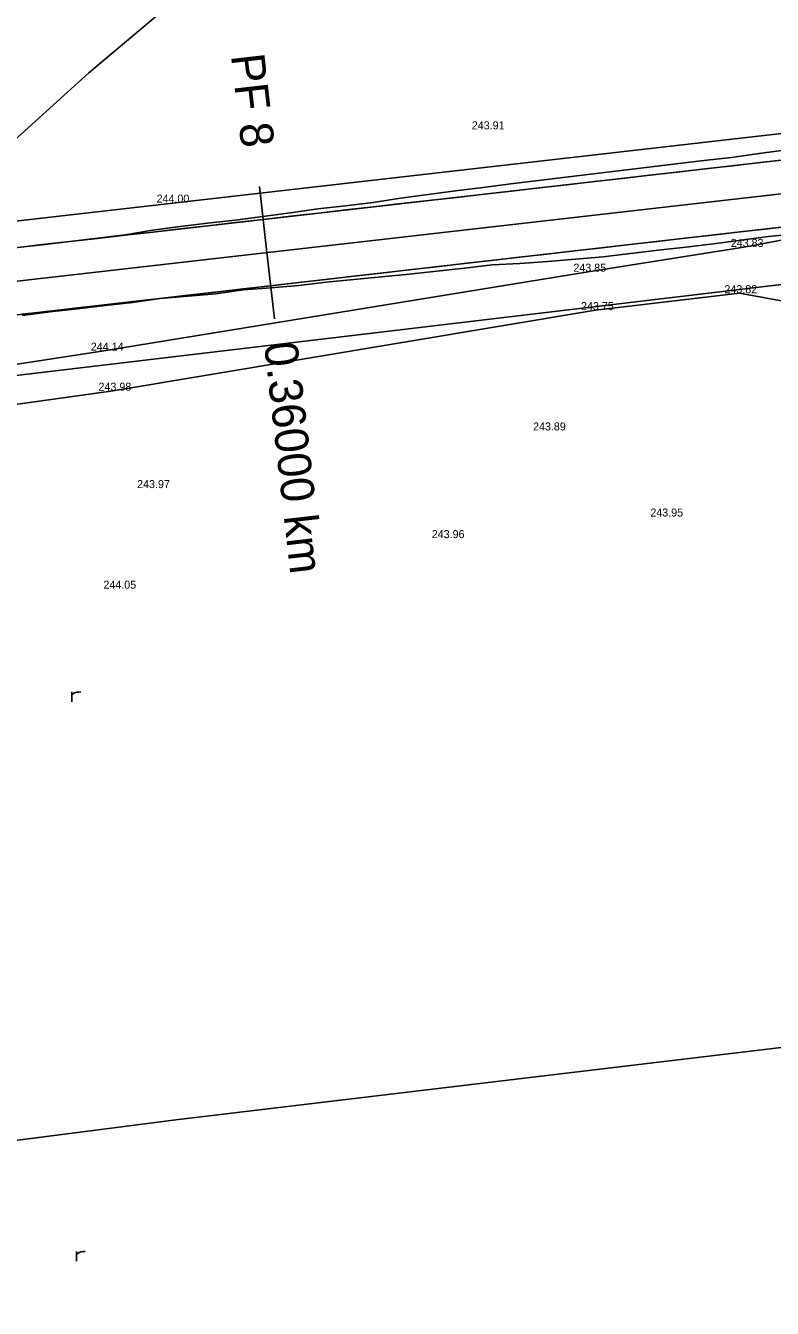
# Model space of a CAD drawing. Extents: x -555887 to -552101, y -1100251 to -1096546.
# Drawn here: x -554433.8 to -554377.8, y -1097745.7 to -1097649.6 of the extents above; entities that cross this region are included whole.
import ezdxf

# ---------------------------------------------------------------- set-up
doc = ezdxf.new("R2010")
doc.units = 0
for name, color, linetype in [('PARCELY_cesty', 7, 'Continuous'), ('POLYGONY_SITUACE_PF', 7, 'Continuous'), ('POLYGONY_SITUACE_PF_POPISY', 7, 'Continuous'), ('POLYGONY_SITUACE_PO', 7, 'Continuous'), ('vrstevnice', 7, 'Continuous'), ('Výškopis', 7, 'Continuous'), ('ZSST', 7, 'Continuous'), ('zájem', 7, 'Continuous')]:
    doc.layers.add(name, color=color, linetype=linetype)

msp = doc.modelspace()

# ---------------------------------------------------------------- linework, layer by layer
at = {"layer": 'PARCELY_cesty'}
msp.add_lwpolyline([(-554491.8, -1097670.76), (-554258.37, -1097644.02)], dxfattribs=at)
at = {"layer": 'POLYGONY_SITUACE_PF'}
for p, q in [((-554416.301, -1097661.61), (-554415.732, -1097666.578)), ((-554415.732, -1097666.578), (-554415.163, -1097671.545))]:
    msp.add_line(p, q, dxfattribs=at)
at = {"layer": 'POLYGONY_SITUACE_PO'}
for p, q in [((-554247.533, -1097644.797), (-554424.295, -1097665.042)), ((-554490.653, -1097675.159), (-554241.626, -1097646.637)), ((-554444.424, -1097672.38), (-554255.551, -1097650.748)), ((-554380.901, -1097659.437), (-554382.97, -1097659.685)), ((-554378.837, -1097659.153), (-554380.901, -1097659.437)), ((-554376.772, -1097658.87), (-554378.837, -1097659.153)), ((-554378.76, -1097659.827), (-554376.69, -1097659.59)), ((-554389.178, -1097660.411), (-554391.245, -1097660.665)), ((-554387.109, -1097660.164), (-554389.178, -1097660.411)), ((-554385.04, -1097659.922), (-554387.109, -1097660.164)), ((-554387.039, -1097660.775), (-554384.969, -1097660.538)), ((-554382.97, -1097659.685), (-554385.04, -1097659.922)), ((-554384.969, -1097660.538), (-554382.899, -1097660.301)), ((-554382.899, -1097660.301), (-554380.829, -1097660.064)), ((-554380.829, -1097660.064), (-554378.76, -1097659.827)), ((-554397.45, -1097661.421), (-554399.515, -1097661.693)), ((-554395.382, -1097661.163), (-554397.45, -1097661.421)), ((-554393.314, -1097660.916), (-554395.382, -1097661.163)), ((-554395.318, -1097661.723), (-554393.248, -1097661.486)), ((-554391.245, -1097660.665), (-554393.314, -1097660.916)), ((-554393.248, -1097661.486), (-554391.178, -1097661.249)), ((-554391.178, -1097661.249), (-554389.109, -1097661.012)), ((-554389.109, -1097661.012), (-554387.039, -1097660.775)), ((-554405.713, -1097662.509), (-554407.774, -1097662.82)), ((-554403.649, -1097662.217), (-554405.713, -1097662.509)), ((-554401.583, -1097661.947), (-554403.649, -1097662.217)), ((-554403.597, -1097662.672), (-554401.527, -1097662.435)), ((-554399.515, -1097661.693), (-554401.583, -1097661.947)), ((-554401.527, -1097662.435), (-554399.458, -1097662.197)), ((-554399.458, -1097662.197), (-554397.388, -1097661.96)), ((-554397.388, -1097661.96), (-554395.318, -1097661.723)), ((-554411.913, -1097663.301), (-554413.977, -1097663.589)), ((-554409.842, -1097663.07), (-554411.913, -1097663.301)), ((-554411.876, -1097663.62), (-554409.807, -1097663.383)), ((-554407.774, -1097662.82), (-554409.842, -1097663.07)), ((-554409.807, -1097663.383), (-554407.737, -1097663.146)), ((-554407.737, -1097663.146), (-554405.667, -1097662.909)), ((-554405.667, -1097662.909), (-554403.597, -1097662.672)), ((-554420.178, -1097664.375), (-554422.245, -1097664.632)), ((-554418.108, -1097664.142), (-554420.178, -1097664.375)), ((-554420.156, -1097664.568), (-554418.086, -1097664.331)), ((-554416.04, -1097663.882), (-554418.108, -1097664.142)), ((-554418.086, -1097664.331), (-554416.016, -1097664.094)), ((-554413.977, -1097663.589), (-554416.04, -1097663.882)), ((-554416.016, -1097664.094), (-554413.946, -1097663.857)), ((-554413.946, -1097663.857), (-554411.876, -1097663.62)), ((-554426.37, -1097665.237), (-554428.436, -1097665.506)), ((-554428.435, -1097665.516), (-554426.365, -1097665.279)), ((-554426.365, -1097665.279), (-554428.435, -1097665.516)), ((-554424.313, -1097664.889), (-554426.37, -1097665.237)), ((-554426.365, -1097665.279), (-554424.295, -1097665.042)), ((-554424.295, -1097665.042), (-554426.365, -1097665.279)), ((-554422.245, -1097664.632), (-554424.313, -1097664.889)), ((-554424.295, -1097665.042), (-554422.225, -1097664.805)), ((-554422.225, -1097664.805), (-554420.156, -1097664.568)), ((-554384.4, -1097665.506), (-554382.33, -1097665.269)), ((-554382.33, -1097665.269), (-554380.26, -1097665.031)), ((-554380.26, -1097665.031), (-554378.191, -1097664.794)), ((-554380.191, -1097665.641), (-554378.123, -1097665.382)), ((-554378.191, -1097664.794), (-554376.121, -1097664.557)), ((-554378.123, -1097665.382), (-554376.05, -1097665.174)), ((-554434.644, -1097666.227), (-554432.574, -1097665.99)), ((-554432.574, -1097665.99), (-554434.644, -1097666.227)), ((-554432.577, -1097665.971), (-554433.948, -1097666.148)), ((-554430.505, -1097665.746), (-554432.577, -1097665.971)), ((-554432.574, -1097665.99), (-554430.505, -1097665.753)), ((-554430.505, -1097665.753), (-554432.574, -1097665.99)), ((-554428.436, -1097665.506), (-554430.505, -1097665.746)), ((-554430.505, -1097665.753), (-554428.435, -1097665.516)), ((-554428.435, -1097665.516), (-554430.505, -1097665.753)), ((-554392.679, -1097666.454), (-554390.609, -1097666.217)), ((-554390.609, -1097666.217), (-554388.54, -1097665.98)), ((-554388.54, -1097665.98), (-554386.47, -1097665.743)), ((-554386.47, -1097665.743), (-554384.4, -1097665.506)), ((-554386.394, -1097666.406), (-554384.323, -1097666.176)), ((-554384.323, -1097666.176), (-554382.255, -1097665.926)), ((-554382.255, -1097665.926), (-554380.191, -1097665.641)), ((-554400.959, -1097667.402), (-554398.889, -1097667.165)), ((-554398.889, -1097667.165), (-554396.819, -1097666.928)), ((-554396.819, -1097666.928), (-554394.749, -1097666.691)), ((-554396.767, -1097667.383), (-554394.686, -1097667.241)), ((-554394.749, -1097666.691), (-554392.679, -1097666.454)), ((-554394.686, -1097667.241), (-554392.608, -1097667.073)), ((-554392.608, -1097667.073), (-554390.531, -1097666.9)), ((-554390.531, -1097666.9), (-554388.464, -1097666.638)), ((-554388.464, -1097666.638), (-554386.394, -1097666.406)), ((-554409.238, -1097668.35), (-554407.168, -1097668.113)), ((-554407.168, -1097668.113), (-554405.098, -1097667.876)), ((-554407.136, -1097668.395), (-554405.063, -1097668.182)), ((-554405.098, -1097667.876), (-554403.028, -1097667.639)), ((-554405.063, -1097668.182), (-554402.991, -1097667.969)), ((-554403.028, -1097667.639), (-554400.959, -1097667.402)), ((-554402.991, -1097667.969), (-554400.918, -1097667.755)), ((-554400.918, -1097667.755), (-554398.851, -1097667.496)), ((-554398.851, -1097667.496), (-554396.767, -1097667.383)), ((-554417.517, -1097669.299), (-554415.447, -1097669.061)), ((-554417.508, -1097669.38), (-554415.43, -1097669.214)), ((-554415.447, -1097669.061), (-554413.377, -1097668.824)), ((-554415.43, -1097669.214), (-554413.353, -1097669.033)), ((-554413.377, -1097668.824), (-554411.308, -1097668.587)), ((-554413.353, -1097669.033), (-554411.284, -1097668.796)), ((-554411.308, -1097668.587), (-554409.238, -1097668.35)), ((-554411.284, -1097668.796), (-554409.208, -1097668.606)), ((-554409.208, -1097668.606), (-554407.136, -1097668.395)), ((-554427.866, -1097670.484), (-554425.796, -1097670.247)), ((-554425.796, -1097670.247), (-554423.726, -1097670.01)), ((-554425.787, -1097670.329), (-554423.927, -1097670.033)), ((-554423.927, -1097670.033), (-554423.725, -1097670.018)), ((-554423.726, -1097670.01), (-554421.657, -1097669.773)), ((-554423.725, -1097670.018), (-554421.649, -1097669.836)), ((-554421.657, -1097669.773), (-554419.587, -1097669.536)), ((-554421.649, -1097669.836), (-554419.572, -1097669.666)), ((-554419.587, -1097669.536), (-554417.517, -1097669.299)), ((-554419.572, -1097669.666), (-554417.508, -1097669.38)), ((-554434.075, -1097671.195), (-554432.006, -1097670.958)), ((-554434.065, -1097671.281), (-554431.997, -1097671.029)), ((-554432.006, -1097670.958), (-554429.936, -1097670.721)), ((-554431.997, -1097671.029), (-554429.928, -1097670.791)), ((-554429.936, -1097670.721), (-554427.866, -1097670.484)), ((-554429.928, -1097670.791), (-554427.858, -1097670.55)), ((-554427.858, -1097670.55), (-554425.787, -1097670.329))]:
    msp.add_line(p, q, dxfattribs=at)
at = {"layer": 'vrstevnice'}
msp.add_lwpolyline([(-554436.587, -1097659.868), (-554429.094, -1097653.099), (-554419.995, -1097645.438)], dxfattribs=at)
at = {"layer": 'ZSST'}
for points in [[(-554454.89, -1097678.09), (-554427.97, -1097673.93), (-554391.64, -1097668.01), (-554379.83, -1097666.15), (-554367.55, -1097663.84)], [(-554375.07, -1097675.34), (-554376.48, -1097670.31), (-554380.31, -1097669.62), (-554391.09, -1097670.89), (-554427.26, -1097676.93), (-554454.67, -1097680.77), (-554487.61, -1097685.6), (-554502.67, -1097687.9), (-554507.97, -1097691.12), (-554509.75, -1097693.98), (-554508.52, -1097711.87), (-554506.18, -1097742.54), (-554505.38, -1097760.57), (-554505.26, -1097765.99), (-554503.94, -1097783.38), (-554503.38, -1097798.36), (-554502.89, -1097806.7), (-554501.1, -1097825.65), (-554499.52, -1097860.36), (-554498.38, -1097882.55), (-554497.18, -1097896.97), (-554493.27, -1097934.67), (-554492.2, -1097940.22), (-554491.25, -1097941.81)], [(-554376.48, -1097670.31), (-554375.76, -1097675.27), (-554372.91, -1097697.64), (-554372.08, -1097704.42), (-554369.85, -1097725.28), (-554422.57, -1097731.58), (-554455.2, -1097735.79), (-554506.18, -1097742.54)], [(-554430.357, -1097700.239), (-554430.357, -1097699.507)], [(-554430.357, -1097699.743), (-554430.255, -1097699.648), (-554430.152, -1097699.585), (-554429.995, -1097699.538), (-554429.845, -1097699.515), (-554429.688, -1097699.507)], [(-554430.017, -1097742.183), (-554430.017, -1097741.451)], [(-554430.017, -1097741.687), (-554429.915, -1097741.592), (-554429.812, -1097741.529), (-554429.655, -1097741.482), (-554429.505, -1097741.459), (-554429.348, -1097741.451)]]:
    msp.add_lwpolyline(points, dxfattribs=at)
at = {"layer": 'zájem'}
msp.add_lwpolyline([(-554254.33, -1097646.97), (-554361.88, -1097662.34), (-554361.52, -1097666.83), (-554371.48, -1097668.3), (-554500.56, -1097683.64)], dxfattribs=at)

# ---------------------------------------------------------------- texts
at = {"layer": 'POLYGONY_SITUACE_PF_POPISY'}
for s, p in [('PF 8', (-554418.432, -1097651.789)), ('0.36000 km', (-554415.957, -1097673.401))]:
    msp.add_text(s, height=2.5, rotation=276.5337, dxfattribs=at).set_placement(p)
at = {"layer": 'Výškopis'}
for s, p in [('243.91', (-554400.372, -1097657.34)), ('244.00', (-554424.005, -1097662.83)), ('243.83', (-554380.958, -1097666.15)), ('243.85', (-554392.756, -1097668.01)), ('243.82', (-554381.434, -1097669.62)), ('243.75', (-554392.186, -1097670.89)), ('244.14', (-554428.936, -1097673.93)), ('243.98', (-554428.36, -1097676.93)), ('243.89', (-554395.782, -1097679.91)), ('243.97', (-554425.463, -1097684.23)), ('243.95', (-554386.988, -1097686.36)), ('243.96', (-554403.374, -1097687.98)), ('244.05', (-554427.99, -1097691.77))]:
    msp.add_text(s, height=0.6, dxfattribs=at).set_placement(p)

doc.saveas('drawing.dxf')
